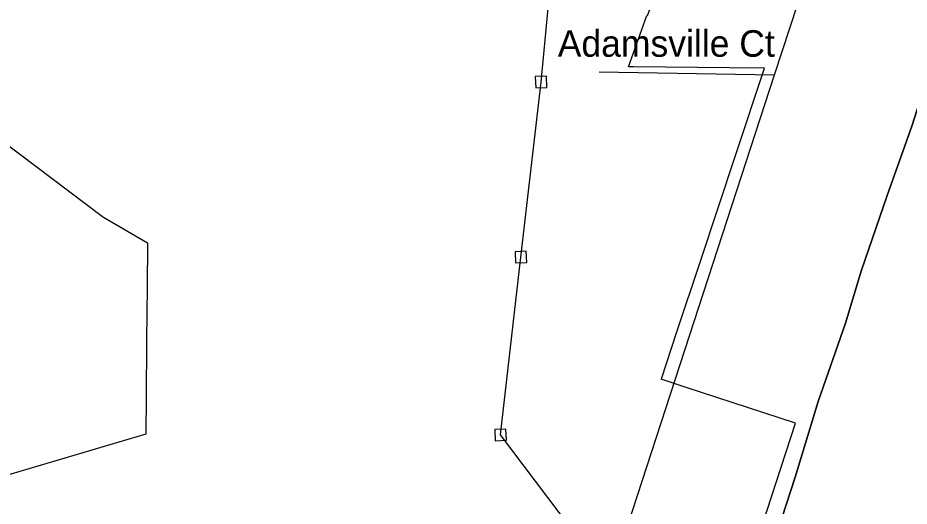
# Model space of a CAD drawing. Extents: x 2220236 to 2384410, y 720751 to 894131.
# Drawn here: x 2348374 to 2351563, y 783259 to 785007 of the extents above; entities that cross this region are included whole.
import ezdxf

# ---------------------------------------------------------------- set-up
doc = ezdxf.new("R2010")
doc.units = 0
doc.layers.add('Default', color=7, linetype='Continuous')

msp = doc.modelspace()

# ---------------------------------------------------------------- linework, layer by layer
at = {"layer": 'Default'}
msp.add_line((2350453.8, 784814), (2351081.3, 784803.5), dxfattribs=at)
for points in [[(2350869.9, 782495.5), (2350436.8, 783070.4), (2350101.5, 783514.1), (2350174, 784150.7), (2350246.2, 784777.5), (2350304.8, 785395.9), (2350020.7, 786086.2), (2349800.8, 786581.5), (2349578.7, 787102.6), (2349360.6, 787617.7), (2349132.2, 788154.8), (2348908.1, 788664.1), (2348869.5, 789213.3), (2348832.1, 789830.7), (2348791.1, 790408), (2348767.9, 790843.5), (2348707.3, 791564.5), (2348681.9, 792186.1)], [(2351061.6, 783072.7), (2351155.6, 783362.5), (2351238.2, 783633.3), (2351335, 783914.5), (2351391, 784099.8), (2351484.1, 784371.5), (2351572.4, 784619.5), (2351656.9, 784880.8), (2351756.6, 785180.1), (2351845.8, 785446.1), (2351966.4, 785827.1), (2352041.4, 786067.5), (2352121.1, 786306.9), (2352213.2, 786591), (2352296.8, 786845.6), (2352375.6, 787093.6), (2352444, 787295), (2352526.6, 787562)], [(2352526.6, 787562), (2352444, 787295), (2352375.6, 787093.6), (2352296.8, 786845.6), (2352213.2, 786591), (2352121.1, 786306.9), (2352041.4, 786067.5), (2351966.4, 785827.1), (2351845.8, 785446.1), (2351756.6, 785180.1), (2351656.9, 784880.8), (2351572.4, 784619.5), (2351484.1, 784371.5), (2351391, 784099.8), (2351335, 783914.5), (2351238.2, 783633.3), (2351155.6, 783362.5), (2351061.6, 783072.7)], [(2349423.6, 779733.7), (2349826, 780958.2), (2350004.8, 781494.8), (2350260.7, 782295.8), (2350506.4, 783037.3), (2351081.3, 784803.5), (2351440.4, 785897.5), (2351562, 786262.8)], [(2350851.2, 782618.4), (2351157, 783556.1), (2350820.5, 783666.4), (2350769, 783682.6), (2350676.5, 783714), (2350678.2, 783718.9), (2350731.2, 783879.1), (2350816.2, 784135.9), (2350879.8, 784327.2), (2350943.2, 784518.6), (2351045.5, 784827.2), (2350920.5, 784828.3), (2350577.5, 784831.3), (2350559.2, 784831.9), (2350624.2, 785015.2), (2350627.2, 785015.2), (2350697.2, 785196.8)], [(2350851.2, 782618.4), (2351157, 783556.1), (2350820.5, 783666.4), (2350769, 783682.6), (2350676.5, 783714), (2350678.2, 783718.9), (2350731.2, 783879.1), (2350816.2, 784135.9), (2350879.8, 784327.2), (2350943.2, 784518.6), (2351045.5, 784827.2), (2350920.5, 784828.3), (2350577.5, 784831.3), (2350559.2, 784831.9), (2350624.2, 785015.2), (2350627.2, 785015.2), (2350697.2, 785196.8)], [(2350227.1, 784756.7), (2350267, 784758.3), (2350265.4, 784798.3), (2350225.4, 784796.7), (2350227.1, 784756.7)], [(2348256.8, 784612.1), (2348677.5, 784295.6), (2348680.2, 784293.6), (2348838, 784201.6), (2348838, 784198.6), (2348836.5, 784044.8), (2348834.8, 783853), (2348834.8, 783846.2), (2348832.8, 783650.1), (2348831.5, 783516.9), (2348251.8, 783344.4)], [(2348256.8, 784612.1), (2348677.5, 784295.6), (2348680.2, 784293.6), (2348838, 784201.6), (2348838, 784198.6), (2348836.5, 784044.8), (2348834.8, 783853), (2348834.8, 783846.2), (2348832.8, 783650.1), (2348831.5, 783516.9), (2348251.8, 783344.4)], [(2350154.8, 784129.9), (2350194.8, 784131.5), (2350193.1, 784171.5), (2350153.2, 784169.8), (2350154.8, 784129.9)], [(2350082.3, 783493.3), (2350122.3, 783494.9), (2350120.7, 783534.9), (2350080.7, 783533.2), (2350082.3, 783493.3)]]:
    msp.add_lwpolyline(points, dxfattribs=at)

# ---------------------------------------------------------------- texts
msp.add_text('Adamsville Ct', height=95, dxfattribs=at).set_placement((2350306, 784868))

doc.saveas('drawing.dxf')
